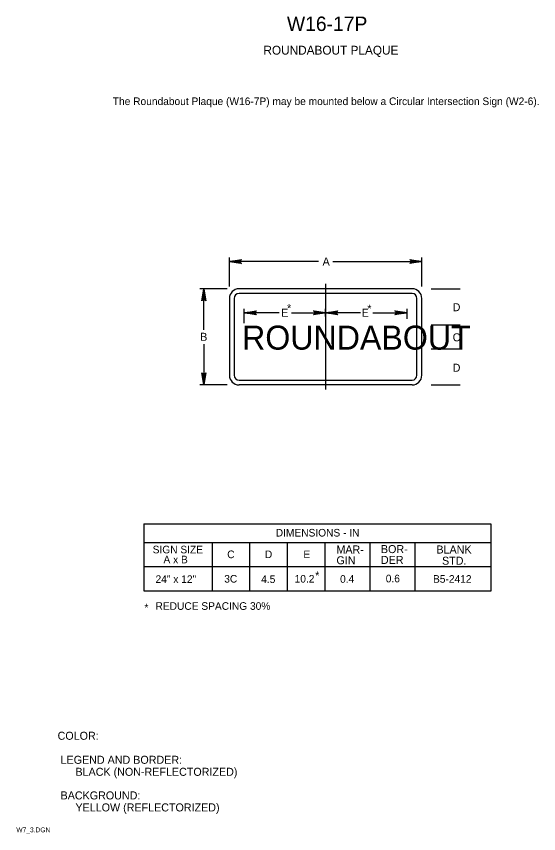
# Model space of a CAD drawing. Extents: x 0.013 to 0.176, y 0.004 to 0.259.
import ezdxf

# ---------------------------------------------------------------- set-up
doc = ezdxf.new("R2010")
doc.units = 0
for name, color, linetype in [('1', 7, 'Continuous'), ('2', 7, 'Continuous'), ('3', 7, 'Continuous')]:
    doc.layers.add(name, color=color, linetype=linetype)

# ---------------------------------------------------------------- blocks, each defined once
blk = doc.blocks.new('RARROW')
at = {"layer": '3'}
for p, q in [((-2.156, 0.285), (-2.2665, 0.384625)), ((-2.2665, 0.384625), (0, 0)), ((0, 0), (-2.2665, -0.379125)), ((-2.156, 0.285), (-2.075625, 0.12075)), ((0, 0), (-2.156, 0.285)), ((-2.14975, -0.2705), (0, 0)), ((-2.075625, 0.12075), (0, 0)), ((0, 0), (-2.074, -0.108)), ((-2.2665, -0.379125), (-2.14975, -0.2705)), ((-2.074, -0.108), (-2.14975, -0.2705))]:
    blk.add_line(p, q, dxfattribs=at)

msp = doc.modelspace()

# ---------------------------------------------------------------- linework, layer by layer
at = {"layer": '1'}
msp.add_line((0.1091, 0.17553), (0.1091, 0.1426), dxfattribs=at)
at = {"layer": '3'}
for p, q in [((0.0791, 0.17478), (0.0791, 0.18378)), ((0.1391, 0.17478), (0.1391, 0.18378)), ((0.1069, 0.18253), (0.0791, 0.18253)), ((0.11131, 0.18253), (0.1391, 0.18253)), ((0.07835, 0.17403), (0.06985, 0.17403)), ((0.0711, 0.16118), (0.0711, 0.17403)), ((0.1361, 0.17403), (0.0821, 0.17403)), ((0.14198, 0.17403), (0.1511, 0.17403)), ((0.0791, 0.17103), (0.0791, 0.14703)), ((0.0806, 0.17103), (0.0806, 0.14703)), ((0.1361, 0.17253), (0.0821, 0.17253)), ((0.1376, 0.14703), (0.1376, 0.17103)), ((0.1391, 0.14703), (0.1391, 0.17103)), ((0.08373, 0.16327), (0.08373, 0.16777)), ((0.09466, 0.16652), (0.08373, 0.16652)), ((0.09843, 0.16652), (0.1091, 0.16652)), ((0.1091, 0.1654), (0.1091, 0.16777)), ((0.11993, 0.16652), (0.1091, 0.16652)), ((0.12383, 0.16652), (0.13449, 0.16652)), ((0.13449, 0.16465), (0.13449, 0.16777)), ((0.14198, 0.16278), (0.1511, 0.16278)), ((0.0711, 0.15678), (0.0711, 0.14403)), ((0.14198, 0.15528), (0.1511, 0.15528)), ((0.0821, 0.14553), (0.1361, 0.14553)), ((0.07835, 0.14403), (0.06985, 0.14403)), ((0.1361, 0.14403), (0.0821, 0.14403)), ((0.14198, 0.14403), (0.1511, 0.14403)), ((0.0524, 0.10069), (0.0524, 0.07969)), ((0.0524, 0.10069), (0.1606, 0.10069)), ((0.1606, 0.10064), (0.1606, 0.07964)), ((0.0524, 0.09482), (0.1606, 0.09482)), ((0.07369, 0.09487), (0.07369, 0.07969)), ((0.0854, 0.09482), (0.0854, 0.07969)), ((0.09715, 0.09482), (0.09715, 0.07969)), ((0.1089, 0.09482), (0.1089, 0.07969)), ((0.1229, 0.09482), (0.1229, 0.07964)), ((0.1369, 0.09482), (0.1369, 0.07964)), ((0.0524, 0.08732), (0.1606, 0.08732)), ((0.0524, 0.07969), (0.1606, 0.07969))]:
    msp.add_line(p, q, dxfattribs=at)
for centre, radius, start, end in [((0.0821, 0.17103), 0.003, 90, 180), ((0.1361, 0.17103), 0.003, 0, 90), ((0.0821, 0.17103), 0.0015, 90, 180), ((0.1361, 0.17103), 0.0015, 0, 90), ((0.0821, 0.14703), 0.003, 180, 270), ((0.0821, 0.14703), 0.0015, 180, 270), ((0.1361, 0.14703), 0.003, 270, 0), ((0.1361, 0.14703), 0.0015, 270, 0)]:
    msp.add_arc(centre, radius, start, end, dxfattribs=at)

# ---------------------------------------------------------------- block references
at = {"layer": '3', "xscale": 0.0016545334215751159, "yscale": 0.0016366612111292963}
for p, rotation in [((0.0791, 0.18253), 180), ((0.0711, 0.17403), 90), ((0.08373, 0.16652), 180), ((0.1091, 0.16652), 180), ((0.0711, 0.14404), -90)]:
    msp.add_blockref('RARROW', p, dxfattribs=dict(at, rotation=rotation))
for p in [(0.1391, 0.18253), (0.1091, 0.16652), (0.13449, 0.16652)]:
    msp.add_blockref('RARROW', p, dxfattribs=at)

# ---------------------------------------------------------------- texts
at = {"layer": '1'}
for s, height, p in [('W16-17P', 0.0045, (0.09703, 0.2545)), ('ROUNDABOUT PLAQUE', 0.0027503, (0.0897, 0.24713)), ('COLOR:', 0.0025, (0.0255, 0.03325)), (' LEGEND AND BORDER:', 0.0024998, (0.0255, 0.02575)), ('      BLACK (NON-REFLECTORIZED)', 0.0024998, (0.0255, 0.022)), (' BACKGROUND:', 0.0024998, (0.0255, 0.01463)), ('      YELLOW (REFLECTORIZED)', 0.0024998, (0.0255, 0.01088)), ('W7_3.DGN', 0.0015, (0.01263, 0.00438))]:
    msp.add_text(s, height=height, dxfattribs=at).set_placement(p)
at = {"layer": '2'}
msp.add_text('The Roundabout Plaque (W16-7P) may be mounted below a Circular Intersection Sign (W2-6).', height=0.0023752, dxfattribs=at).set_placement((0.04272, 0.23137))
at = {"layer": '3'}
for s, height, p in [('A', 0.0025, (0.10815, 0.18128)), ('*', 0.0025, (0.09707, 0.16673)), ('*', 0.0025, (0.1221, 0.1666)), ('D', 0.0025, (0.14873, 0.16702)), ('E', 0.0025, (0.09524, 0.16527)), ('E', 0.0025, (0.12034, 0.16527)), ('ROUNDABOUT', 0.0075, (0.08304, 0.15503)), ('B', 0.0025, (0.06998, 0.15778)), ('C', 0.0025, (0.14873, 0.15762)), ('D', 0.0025, (0.14873, 0.14814)), ('DIMENSIONS - IN', 0.0023752, (0.09354, 0.09669)), ('SIGN SIZE', 0.002375, (0.05515, 0.09144)), ('C', 0.00238, (0.0784, 0.08994)), ('D', 0.00238, (0.09015, 0.08994)), ('E', 0.00238, (0.10215, 0.08994)), ('MAR-', 0.0025, (0.11248, 0.09139)), ('BOR-', 0.0025, (0.12635, 0.09152)), ('BLANK', 0.0025, (0.14366, 0.09139)), ('A x B', 0.002375, (0.05852, 0.08832)), ('GIN', 0.0025, (0.11248, 0.08802)), ('DER', 0.0025, (0.12635, 0.08814)), ('STD.', 0.0025, (0.14541, 0.08789)), ('24" x 12"', 0.002375, (0.05605, 0.08219)), ('3C', 0.002375, (0.07748, 0.08231)), ('4.5', 0.002375, (0.089, 0.08219)), ('10.2', 0.002375, (0.09943, 0.08231)), ('*', 0.0025, (0.10585, 0.08328)), ('0.4', 0.002375, (0.1136, 0.08226)), ('0.6', 0.002375, (0.12786, 0.08239)), ('B5-2412', 0.002375, (0.1426, 0.08226)), ('*', 0.00238, (0.05259, 0.07331)), ('REDUCE SPACING 30%', 0.0023752, (0.05604, 0.07381))]:
    msp.add_text(s, height=height, dxfattribs=at).set_placement(p)

doc.saveas('drawing.dxf')
